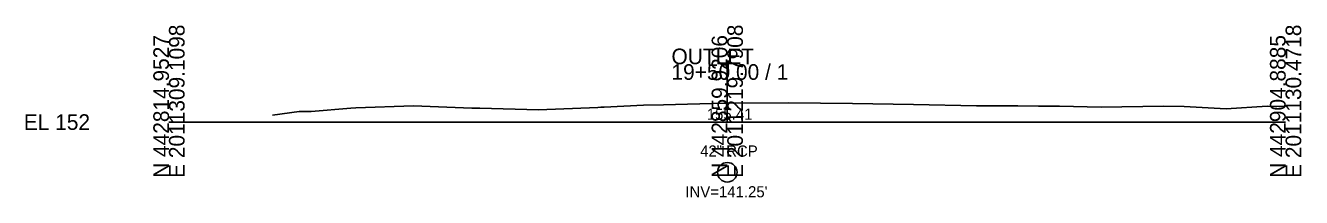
# Model space of a CAD drawing. Extents: x -26 to 1203, y -15 to 9526.
# Drawn here: x -25.7 to 202.8, y 9486.5 to 9517.3 of the extents above; entities that cross this region are included whole.
import ezdxf

# ---------------------------------------------------------------- set-up
doc = ezdxf.new("R2010")
doc.units = 0
for name, color, linetype in [('Exist Cross Section Cell', 7, 'Continuous'), ('Exist XS Center Line Elevation Label', 7, 'Continuous'), ('Exist XS Ground Line', 7, 'Continuous'), ('Prop XSC Text', 7, 'Continuous')]:
    doc.layers.add(name, color=color, linetype=linetype)

msp = doc.modelspace()

# ---------------------------------------------------------------- linework, layer by layer
at = {"layer": 'Exist Cross Section Cell'}
for p, q in [((100, 9500), (100, 9510.38)), ((0, 9500), (100, 9500)), ((100, 9500), (200, 9500))]:
    msp.add_line(p, q, dxfattribs=at)
at = {"layer": 'Exist XS Ground Line'}
msp.add_lwpolyline([(18.52, 9501.22), (23.31, 9501.89), (24.43, 9501.88), (25.44, 9501.92), (32.59, 9502.49), (33.46, 9502.54), (43.79, 9502.94), (54.25, 9502.51), (54.98, 9502.5), (55.7, 9502.47), (66.18, 9502.18), (76.8, 9502.63), (77.37, 9502.65), (77.94, 9502.68), (85.01, 9503.02), (88.57, 9503.12), (99.35, 9503.39), (100.18, 9503.41), (110.96, 9503.46), (122.41, 9503.31), (133.35, 9503.18), (144.65, 9502.93), (152.03, 9502.91), (155.74, 9502.84), (159.48, 9502.85), (166.99, 9502.7), (178.14, 9502.87), (181.82, 9502.82), (189.33, 9502.36), (196.71, 9502.83), (200, 9502.81)], dxfattribs=at)
at = {"layer": 'Prop XSC Text'}
msp.add_circle((100, 9491), 1.75, dxfattribs=at)

# ---------------------------------------------------------------- texts
at = {"layer": 'Exist Cross Section Cell'}
for s, p in [('E 2011309.1098', (2.8, 9490)), ('E 2011219.7908', (102.8, 9490)), ('E 2011130.4718', (202.8, 9490)), ('N 442814.9527', (0, 9490)), ('N 442859.9206', (100, 9490)), ('N 442904.8885', (200, 9490))]:
    msp.add_text(s, height=2.8, rotation=90, dxfattribs=at).set_placement(p)
for s, p in [('OUTLET', (90, 9510.38)), ('19+50.00 / 1', (90, 9507.58)), ('EL 152', (-26, 9498.6))]:
    msp.add_text(s, height=2.8, dxfattribs=at).set_placement(p)
at = {"layer": 'Exist XS Center Line Elevation Label'}
msp.add_text('155.41', height=2, dxfattribs=at).set_placement((96.32, 9500.41))
at = {"layer": 'Prop XSC Text'}
for s, p in [('42" RCP', (95.14, 9493.81)), ("INV=141.25'", (92.49, 9486.51))]:
    msp.add_text(s, height=2, dxfattribs=at).set_placement(p)

doc.saveas('drawing.dxf')
